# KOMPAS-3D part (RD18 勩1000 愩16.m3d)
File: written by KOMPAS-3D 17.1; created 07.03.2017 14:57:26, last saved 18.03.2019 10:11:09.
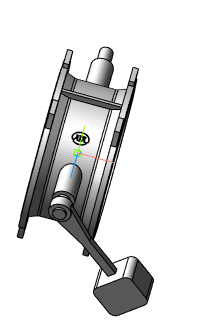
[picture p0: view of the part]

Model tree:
1. Операция без истории:2  (labels: Сталь 20  ГОСТ 1050-88)

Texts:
  RD18 Ду100 Ру16
  RD18 Ду150 Ру16
  RD18 Ду200 Ру16
  RD18 Ду250 Ру16
  RD18 Ду300 Ру16
  RD18 Ду350 Ру16
  RD18 Ду400 Ру10
  RD18 Ду400 Ру16
  RD18 Ду450 Ру10
  RD18 Ду450 Ру16
  RD18 Ду500 Ру10
  RD18 Ду500 Ру16
  RD18 Ду600 Ру10
  RD18 Ду600 Ру16
  RD18 Ду700 Ру10
  RD18 Ду700 Ру16
  RD18 Ду800 Ру10
  RD18 Ду800 Ру16
  RD18 Ду900 Ру10
  RD18 Ду900 Ру16
  RD18 Ду1000 Ру10
  RD18 Ду1000 Ру16
  RD18 Ду1200 Ру16
  RD18 Ду1400 Ру16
